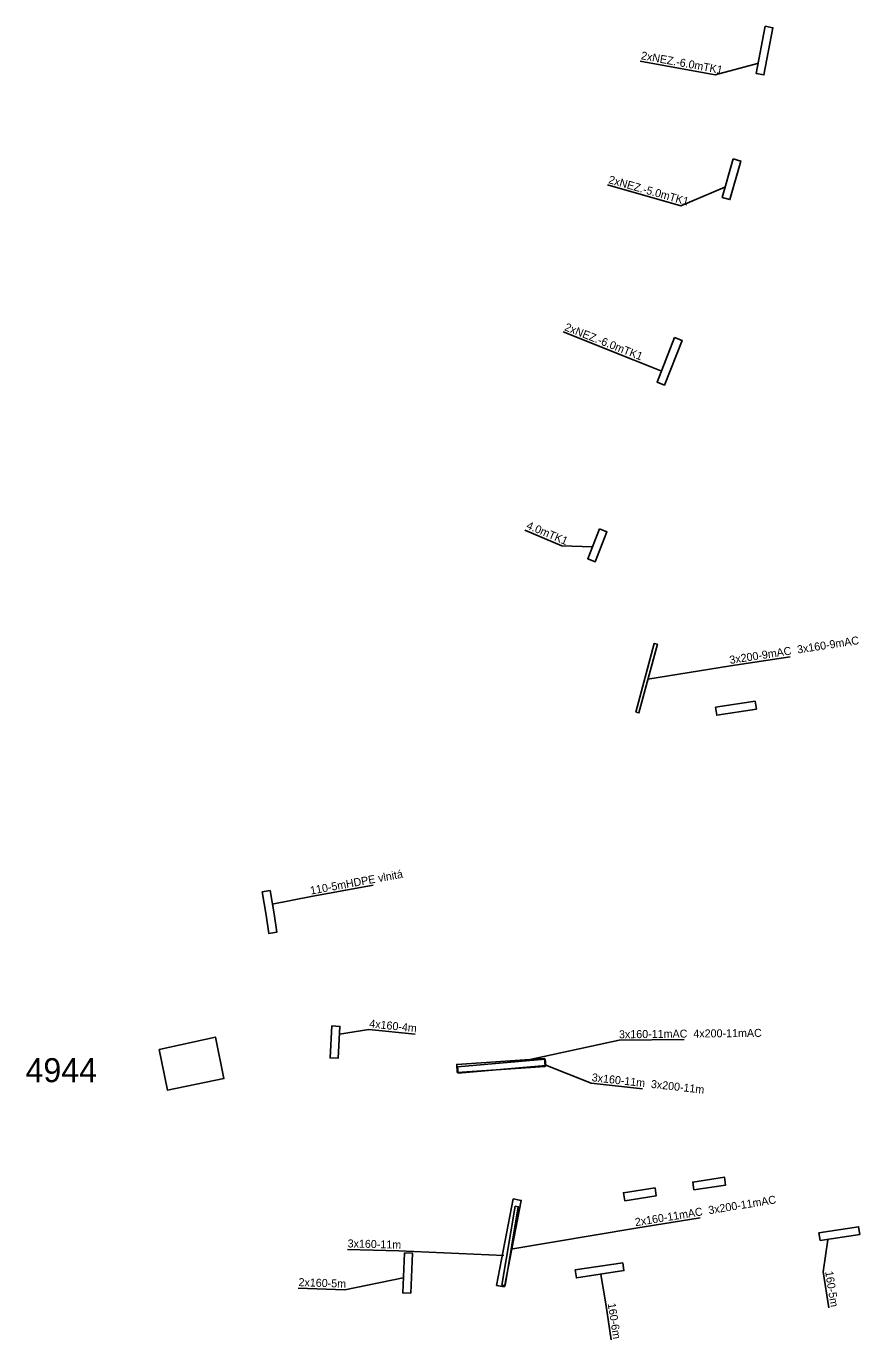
# Model space of a CAD drawing. Extents: x -732155 to -731960, y -1048709 to -1047981.
# Drawn here: x -732104.2 to -732000.1, y -1048327 to -1048162.9 of the extents above; entities that cross this region are included whole.
import ezdxf

# ---------------------------------------------------------------- set-up
doc = ezdxf.new("R2010")
doc.units = 0
for name, color, linetype in [('Chránička', 7, 'Continuous'), ('ST_CHRANICKA_POPIS', 7, 'Continuous'), ('ST_TRAFOSTANICE_POPIS', 7, 'Continuous'), ('TS_RS_R', 7, 'Continuous')]:
    doc.layers.add(name, color=color, linetype=linetype)

msp = doc.modelspace()

# ---------------------------------------------------------------- linework, layer by layer
at = {"layer": 'Chránička'}
for points in [[(-732011.929, -1048162.91), (-732010.947, -1048163.098), (-732012.07, -1048168.992), (-732013.052, -1048168.804), (-732011.929, -1048162.91)], [(-732015.901, -1048179.476), (-732014.939, -1048179.75), (-732016.308, -1048184.559), (-732017.27, -1048184.285), (-732015.901, -1048179.476)], [(-732023.226, -1048201.784), (-732022.294, -1048202.148), (-732024.483, -1048207.734), (-732025.415, -1048207.37), (-732023.226, -1048201.784)], [(-732032.601, -1048225.706), (-732031.669, -1048226.072), (-732033.129, -1048229.796), (-732034.061, -1048229.43), (-732032.601, -1048225.706)], [(-732028.074, -1048248.59), (-732025.759, -1048240.001), (-732025.373, -1048240.105), (-732027.687, -1048248.694), (-732028.074, -1048248.59)], [(-732013.161, -1048247.221), (-732013.009, -1048248.209), (-732017.95, -1048248.972), (-732018.102, -1048247.984), (-732013.161, -1048247.221)], [(-732074.735, -1048271.049), (-732073.75, -1048270.882), (-732073.244, -1048273.795), (-732072.925, -1048276.087), (-732073.907, -1048276.24), (-732074.239, -1048273.968), (-732074.735, -1048271.049)], [(-732066.021, -1048287.785), (-732065.023, -1048287.843), (-732065.254, -1048291.836), (-732066.252, -1048291.778), (-732066.021, -1048287.785)], [(-732050.362, -1048293.589), (-732050.428, -1048292.591), (-732039.452, -1048291.857), (-732039.386, -1048292.855), (-732050.362, -1048293.589)], [(-732039.374, -1048291.957), (-732039.305, -1048292.754), (-732050.277, -1048293.69), (-732050.345, -1048292.893), (-732039.374, -1048291.957)], [(-732020.806, -1048308.282), (-732020.96, -1048307.294), (-732017.007, -1048306.68), (-732016.853, -1048307.668), (-732020.806, -1048308.282)], [(-732029.457, -1048309.626), (-732029.611, -1048308.638), (-732025.658, -1048308.024), (-732025.504, -1048309.012), (-732029.457, -1048309.626)], [(-732044.473, -1048320.397), (-732045.455, -1048320.207), (-732043.367, -1048309.407), (-732042.385, -1048309.597), (-732044.473, -1048320.397)], [(-732043.146, -1048310.316), (-732042.752, -1048310.383), (-732044.397, -1048320.23), (-732044.792, -1048320.164), (-732043.146, -1048310.316)], [(-732005.04, -1048314.616), (-732005.19, -1048313.628), (-732000.247, -1048312.875), (-732000.097, -1048313.863), (-732005.04, -1048314.616)], [(-732056.174, -1048321.19), (-732057.173, -1048321.144), (-732056.944, -1048316.149), (-732055.945, -1048316.195), (-732056.174, -1048321.19)], [(-732029.702, -1048317.367), (-732029.552, -1048318.355), (-732035.483, -1048319.26), (-732035.633, -1048318.272), (-732029.702, -1048317.367)]]:
    msp.add_lwpolyline(points, close=True, dxfattribs=at)
at = {"layer": 'ST_CHRANICKA_POPIS'}
for points in [[(-732027.518, -1048167.265), (-732018.136, -1048168.981), (-732012.852, -1048167.541)], [(-732031.62, -1048182.731), (-732022.446, -1048185.339), (-732016.957, -1048183.005)], [(-732037.141, -1048201.097), (-732028.275, -1048204.611), (-732024.958, -1048205.962)], [(-732041.911, -1048225.865), (-732037.293, -1048227.808), (-732033.532, -1048227.951)], [(-732026.572, -1048244.488), (-732016.246, -1048242.822), (-732008.786, -1048241.67)], [(-732073.498, -1048272.593), (-732068.598, -1048271.633), (-732060.859, -1048270.211)], [(-732065.085, -1048288.802), (-732061.419, -1048288.221), (-732055.616, -1048288.825)], [(-732042.07, -1048292.16), (-732030.162, -1048289.588), (-732022.019, -1048289.506)], [(-732039.289, -1048292.683), (-732033.633, -1048294.937), (-732027.244, -1048295.652)], [(-732043.688, -1048315.681), (-732028.05, -1048313.06), (-732020.012, -1048311.75)], [(-732004.061, -1048314.502), (-732004.668, -1048318.522), (-732003.969, -1048322.998)], [(-732064.081, -1048315.705), (-732057.654, -1048315.869), (-732044.564, -1048316.47)], [(-732070.222, -1048320.539), (-732064.393, -1048320.75), (-732057.127, -1048319.247)], [(-732032.427, -1048318.838), (-732031.827, -1048322.515), (-732031.138, -1048326.992)]]:
    msp.add_lwpolyline(points, dxfattribs=at)
at = {"layer": 'TS_RS_R'}
msp.add_lwpolyline([(-732087.59, -1048290.74), (-732080.58, -1048289.18), (-732079.52, -1048294.37), (-732086.56, -1048295.83), (-732087.59, -1048290.74)], close=True, dxfattribs=at)

# ---------------------------------------------------------------- texts
at = {"layer": 'ST_CHRANICKA_POPIS'}
for s, rotation, p in [('2xNEZ.-6.0mTK1', 349.63709, (-732027.473, -1048167.019)), ('2xNEZ.-5.0mTK1', 344.12719, (-732031.551, -1048182.49)), ('2xNEZ.-6.0mTK1', 338.38269, (-732037.049, -1048200.865)), ('4.0mTK1', 337.18515, (-732041.814, -1048225.635)), ('3x200-9mAC  3x160-9mAC', 8.78093, (-732016.284, -1048242.575)), ('110-5mHDPE vlnitá', 10.41228, (-732068.643, -1048271.387)), ('4x160-4m', 354.05644, (-732061.393, -1048287.972)), ('3x160-11mAC  4x200-11mAC', 0.57911, (-732030.165, -1048289.338)), ('3x160-11m  3x200-11m', 353.61546, (-732033.606, -1048294.689)), ('2x160-11mAC  3x200-11mAC', 9.2602, (-732028.09, -1048312.814)), ('3x160-11m', 358.53428, (-732064.074, -1048315.455)), ('2x160-5m', 357.92964, (-732070.213, -1048320.289)), ('160-5m', 278.8829, (-732004.421, -1048318.484)), ('160-6m', 278.7446, (-732031.579, -1048322.477))]:
    msp.add_text(s, height=1, rotation=rotation, dxfattribs=at).set_placement(p)
at = {"layer": 'ST_TRAFOSTANICE_POPIS'}
msp.add_text('4944', height=3, dxfattribs=at).set_placement((-732104.297, -1048294.818))

doc.saveas('drawing.dxf')
